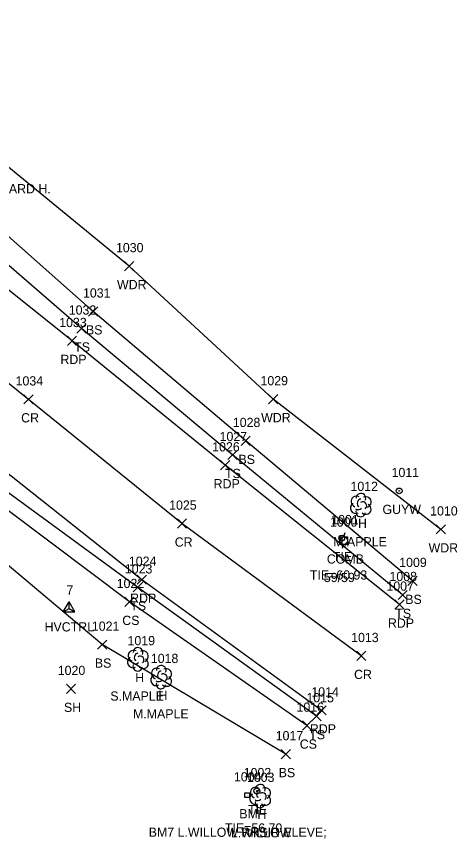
# Model space of a CAD drawing. Extents: x 1537342 to 1542195, y 163002 to 168596.
# Drawn here: x 1542099.6 to 1542195, y 163002.3 to 163180.4 of the extents above; entities that cross this region are included whole.
import ezdxf

# ---------------------------------------------------------------- set-up
doc = ezdxf.new("R2010")
doc.units = 0
for name, color, linetype in [('C_A', 7, 'Continuous'), ('C_C', 7, 'Continuous'), ('C_I', 7, 'Continuous'), ('CBP', 7, 'Continuous'), ('CPBM', 7, 'Continuous'), ('CPSM', 7, 'Continuous'), ('L_A', 7, 'Continuous'), ('L_C', 7, 'Continuous'), ('L_I', 7, 'Continuous'), ('L_TIC', 7, 'Continuous'), ('LAWA', 7, 'Continuous'), ('LELB', 7, 'Continuous'), ('LTD', 7, 'Continuous'), ('M_C', 7, 'Continuous'), ('P_A', 7, 'Continuous'), ('P_I', 7, 'Continuous'), ('P_TIC', 7, 'Continuous'), ('PET', 7, 'Continuous'), ('PRC', 7, 'Continuous'), ('U_A', 7, 'Continuous'), ('U_C', 7, 'Continuous'), ('U_I', 7, 'Continuous'), ('UP', 7, 'Continuous'), ('UPGW', 7, 'Continuous')]:
    doc.layers.add(name, color=color, linetype=linetype)

msp = doc.modelspace()

# ---------------------------------------------------------------- linework, layer by layer
at = {"layer": 'CBP'}
for centre, radius in [((1542169.95, 163067.38), 0.625), ((1542169.95, 163067.38), 0.0833), ((1542151.58, 163012.58), 0.625), ((1542151.58, 163012.58), 0.0833)]:
    msp.add_circle(centre, radius, dxfattribs=at)
at = {"layer": 'CPBM'}
for p, q in [((1542148.96, 163011.16), (1542148.96, 163012.16)), ((1542148.96, 163012.16), (1542149.96, 163012.16)), ((1542149.47, 163011.66), (1542149.47, 163011.66)), ((1542149.47, 163011.66), (1542149.47, 163011.66)), ((1542149.96, 163012.16), (1542149.96, 163011.16)), ((1542149.96, 163011.16), (1542148.96, 163011.16))]:
    msp.add_line(p, q, dxfattribs=at)
at = {"layer": 'CPSM'}
for p, q in [((1542109.7, 163051.42), (1542110.95, 163053.59)), ((1542112.2, 163051.42), (1542110.95, 163053.59)), ((1542110.95, 163052.14), (1542110.95, 163053.59)), ((1542109.7, 163051.42), (1542110.95, 163052.14)), ((1542109.7, 163051.42), (1542112.2, 163051.42)), ((1542110.95, 163052.14), (1542110.95, 163052.14)), ((1542110.95, 163052.14), (1542112.2, 163051.42))]:
    msp.add_line(p, q, dxfattribs=at)
at = {"layer": 'L_TIC'}
for points in [[(1542122.95, 163125.28), (1542124.95, 163127.28)], [(1542124.95, 163125.28), (1542122.95, 163127.28)], [(1542115.16, 163115.47), (1542117.16, 163117.47)], [(1542117.16, 163115.47), (1542115.16, 163117.47)], [(1542112.65, 163111.77), (1542114.65, 163113.77)], [(1542114.65, 163111.77), (1542112.65, 163113.77)], [(1542154.13, 163096.46), (1542156.13, 163098.46)], [(1542156.13, 163096.46), (1542154.13, 163098.46)], [(1542148.16, 163087.42), (1542150.16, 163089.42)], [(1542150.16, 163087.42), (1542148.16, 163089.42)], [(1542145.29, 163084.37), (1542147.29, 163086.37)], [(1542147.29, 163084.37), (1542145.29, 163086.37)], [(1542190.37, 163068.26), (1542192.37, 163070.26)], [(1542192.37, 163068.26), (1542190.37, 163070.26)], [(1542184.24, 163057.1), (1542186.24, 163059.1)], [(1542186.24, 163057.1), (1542184.24, 163059.1)], [(1542124.79, 163055.7), (1542126.79, 163057.7)], [(1542126.79, 163055.7), (1542124.79, 163057.7)], [(1542182.12, 163054.05), (1542184.12, 163056.05)], [(1542184.12, 163054.05), (1542182.12, 163056.05)], [(1542123.02, 163052.54), (1542125.02, 163054.54)], [(1542125.02, 163052.54), (1542123.02, 163054.54)], [(1542117.09, 163043.29), (1542119.09, 163045.29)], [(1542119.09, 163043.29), (1542117.09, 163045.29)], [(1542110.36, 163033.71), (1542112.36, 163035.71)], [(1542112.36, 163033.71), (1542110.36, 163035.71)], [(1542163.5, 163027.8), (1542165.5, 163029.8)], [(1542165.5, 163027.8), (1542163.5, 163029.8)], [(1542161.42, 163025.75), (1542163.42, 163027.75)], [(1542163.42, 163025.75), (1542161.42, 163027.75)], [(1542156.86, 163019.57), (1542158.86, 163021.57)], [(1542158.86, 163019.57), (1542156.86, 163021.57)]]:
    msp.add_lwpolyline(points, dxfattribs=at)
at = {"layer": 'LAWA'}
msp.add_lwpolyline([(1542191.37, 163069.26), (1542155.13, 163097.46), (1542123.95, 163126.28), (1542083.78, 163159.16), (1542082.85, 163172.31), (1542083.05, 163192.11), (1542078.54, 163207.24), (1542059.97, 163213.12), (1542055.91, 163226.6), (1542055.2, 163251.61), (1542037.65, 163282.73), (1542029.16, 163294.8)], dxfattribs=at)
at = {"layer": 'LELB'}
for points in [[(1542185.24, 163058.1), (1542149.16, 163088.42), (1542116.16, 163116.47), (1542076.56, 163151.51), (1542049.16, 163172.67), (1542035.85, 163185.79), (1542036.46, 163200.98), (1542035.82, 163228.32), (1542041.31, 163237.99)], [(1542183.12, 163055.05), (1542146.29, 163085.37), (1542113.65, 163112.77), (1542073.54, 163147.5), (1542044.28, 163168.18), (1542019.33, 163189.82), (1542014.69, 163194.08)], [(1542162.42, 163026.75), (1542124.02, 163053.54), (1542089.63, 163079.43)], [(1542164.5, 163028.8), (1542125.79, 163056.7), (1542093.51, 163080.24)], [(1542157.86, 163020.57), (1542118.09, 163044.29), (1542089.28, 163068.58)]]:
    msp.add_lwpolyline(points, dxfattribs=at)
at = {"layer": 'LTD'}
for p, q in [((1542174.03, 163074.57), (1542174.03, 163074.57)), ((1542174.03, 163074.57), (1542174.03, 163074.57)), ((1542125.81, 163041.16), (1542125.81, 163041.16)), ((1542125.81, 163041.16), (1542125.81, 163041.16)), ((1542130.84, 163037.3), (1542130.84, 163037.3)), ((1542130.84, 163037.3), (1542130.84, 163037.3)), ((1542152.28, 163011.55), (1542152.28, 163011.55)), ((1542152.28, 163011.55), (1542152.28, 163011.55))]:
    msp.add_line(p, q, dxfattribs=at)
for centre in [(1542174.08, 163076), (1542125.86, 163042.6), (1542130.89, 163038.74), (1542152.32, 163012.98)]:
    msp.add_arc(centre, 1.05, 335.5272, 180.9563, dxfattribs=at)
for centre, major_axis, ratio, start_param, end_param in [((1542173.24, 163075.24), (1.21, -0.51), 0.895232, 1.570796, 4.712389), ((1542173.83, 163075.03), (-0.208, -0.792), 0.645439, 3.141593, 6.283185), ((1542175.08, 163075.15), (-1.14, -0.48), 0.949671, 1.570796, 4.712389), ((1542172.95, 163073.86), (0.58, -1.04), 0.959034, 3.141593, 6.283185), ((1542173.58, 163073.82), (-0.625, -0.083), 0.423636, 0, 3.141593), ((1542174.53, 163074.4), (-0.5, 0.667), 0.989748, 3.141593, 6.283185), ((1542175.03, 163073.74), (-1.09, 0.79), 0.841452, 1.570796, 4.712389), ((1542174.03, 163073.07), (0.26, 1.06), 0.942809, 1.570796, 4.712389), ((1542125.02, 163041.83), (1.21, -0.51), 0.895232, 1.570796, 4.712389), ((1542125.61, 163041.62), (-0.208, -0.792), 0.645439, 3.141593, 6.283185), ((1542126.31, 163041), (-0.5, 0.667), 0.989748, 3.141593, 6.283185), ((1542126.86, 163041.75), (-1.14, -0.48), 0.949671, 1.570796, 4.712389), ((1542124.73, 163040.45), (0.58, -1.04), 0.959034, 3.141593, 6.283185), ((1542125.36, 163040.41), (-0.625, -0.083), 0.423636, 0, 3.141593), ((1542126.81, 163040.33), (-1.09, 0.79), 0.841452, 1.570796, 4.712389), ((1542125.81, 163039.66), (0.26, 1.06), 0.942809, 1.570796, 4.712389), ((1542130.05, 163037.97), (1.21, -0.51), 0.895232, 1.570796, 4.712389), ((1542130.64, 163037.76), (-0.208, -0.792), 0.645439, 3.141593, 6.283185), ((1542131.89, 163037.89), (-1.14, -0.48), 0.949671, 1.570796, 4.712389), ((1542129.76, 163036.59), (0.58, -1.04), 0.959034, 3.141593, 6.283185), ((1542130.39, 163036.55), (-0.625, -0.083), 0.423636, 0, 3.141593), ((1542131.34, 163037.14), (-0.5, 0.667), 0.989748, 3.141593, 6.283185), ((1542131.84, 163036.47), (-1.09, 0.79), 0.841452, 1.570796, 4.712389), ((1542130.84, 163035.8), (0.26, 1.06), 0.942809, 1.570796, 4.712389), ((1542151.48, 163012.21), (1.21, -0.51), 0.895232, 1.570796, 4.712389), ((1542153.32, 163012.13), (-1.14, -0.48), 0.949671, 1.570796, 4.712389), ((1542151.19, 163010.84), (0.58, -1.04), 0.959034, 3.141593, 6.283185), ((1542152.07, 163012.01), (-0.208, -0.792), 0.645439, 3.141593, 6.283185), ((1542152.78, 163011.38), (-0.5, 0.667), 0.989748, 3.141593, 6.283185), ((1542153.28, 163010.71), (-1.09, 0.79), 0.841452, 1.570796, 4.712389), ((1542152.28, 163010.05), (0.26, 1.06), 0.942809, 1.570796, 4.712389), ((1542151.82, 163010.8), (-0.625, -0.083), 0.423636, 0, 3.141593)]:
    msp.add_ellipse(centre, major_axis=major_axis, ratio=ratio, start_param=start_param, end_param=end_param, dxfattribs=at)
at = {"layer": 'P_TIC'}
for points in [[(1542110.59, 163109.07), (1542112.59, 163111.07)], [(1542112.59, 163109.07), (1542110.59, 163111.07)], [(1542101.15, 163096.42), (1542103.15, 163098.42)], [(1542103.15, 163096.42), (1542101.15, 163098.42)], [(1542143.74, 163082.14), (1542145.74, 163084.14)], [(1542145.74, 163082.14), (1542143.74, 163084.14)], [(1542134.38, 163069.51), (1542136.38, 163071.51)], [(1542136.38, 163069.51), (1542134.38, 163071.51)], [(1542125.67, 163057.36), (1542127.67, 163059.36)], [(1542127.67, 163057.36), (1542125.67, 163059.36)], [(1542181.46, 163051.97), (1542183.46, 163053.97)], [(1542183.46, 163051.97), (1542181.46, 163053.97)], [(1542173.18, 163040.84), (1542175.18, 163042.84)], [(1542175.18, 163040.84), (1542173.18, 163042.84)], [(1542164.56, 163029.05), (1542166.56, 163031.05)], [(1542166.56, 163029.05), (1542164.56, 163031.05)]]:
    msp.add_lwpolyline(points, dxfattribs=at)
at = {"layer": 'PET'}
for points in [[(1542165.56, 163030.05), (1542126.67, 163058.36), (1542096.32, 163082.47), (1542058.61, 163112.54), (1542052.02, 163117.84), (1542010.73, 163151.35), (1541978.73, 163177.48), (1541958.58, 163193.33), (1541928.58, 163217.89), (1541894.65, 163244.61), (1541857.53, 163271.04), (1541839.6, 163283.45), (1541795.58, 163311.16), (1541814.19, 163318.82), (1541832.22, 163326.69)], [(1542182.46, 163052.97), (1542144.74, 163083.14), (1542111.59, 163110.07), (1542069.86, 163143.45), (1542042.93, 163166.04), (1542014.58, 163189.13), (1541996.52, 163203.32), (1541975.27, 163220.84), (1541953.96, 163238.23), (1541914.85, 163268.66), (1541894.39, 163285), (1541874.19, 163298.08), (1541854.83, 163311.47), (1541832.22, 163326.69)]]:
    msp.add_lwpolyline(points, dxfattribs=at)
at = {"layer": 'PRC'}
msp.add_lwpolyline([(1542174.18, 163041.84), (1542135.38, 163070.51), (1542102.15, 163097.42), (1542058.02, 163132.98), (1542032.76, 163153.88), (1541982.81, 163194.28), (1541947.35, 163222.57), (1541904.32, 163256.11), (1541874.29, 163278.53), (1541825.99, 163311), (1541814.19, 163318.82)], dxfattribs=at)
at = {"layer": 'UP'}
for p, q in [((1542170.59, 163068.51), (1542170.34, 163067.67)), ((1542169.5, 163066.01), (1542169.5, 163067.67)), ((1542169.5, 163067.67), (1542171.17, 163067.67)), ((1542170.34, 163066.84), (1542170.34, 163066.84)), ((1542171.17, 163067.67), (1542171.17, 163066.01)), ((1542171.17, 163066.01), (1542169.5, 163066.01)), ((1542170.09, 163065.17), (1542170.34, 163066.01))]:
    msp.add_line(p, q, dxfattribs=at)
msp.add_circle((1542170.34, 163066.84), 0.833, dxfattribs=at)
at = {"layer": 'UPGW'}
for radius in [0.625, 0.0833]:
    msp.add_circle((1542182.37, 163077.58), radius, dxfattribs=at)

# ---------------------------------------------------------------- texts
at = {"layer": 'C_A'}
for s, p in [('TIE', (1542168.03, 163062.38)), ('HVCTRL', (1542105.65, 163047.14)), ('BM', (1542147.78, 163006.66)), ('TIE', (1542149.66, 163007.58))]:
    msp.add_text(s, height=2, dxfattribs=at).set_placement(p)
at = {"layer": 'C_C'}
for s, p in [('TIE=60.93', (1542163.05, 163058.38)), ('BM7 L.WILLOW RRSIR ELEVE;', (1542128.18, 163002.66)), ('TIE=56.70', (1542144.67, 163003.58))]:
    msp.add_text(s, height=2, dxfattribs=at).set_placement(p)
at = {"layer": 'C_I'}
for s, p in [('1001', (1542167.67, 163070.38)), ('7', (1542110.39, 163055.14)), ('1002', (1542148.73, 163015.58)), ('1004', (1542146.62, 163014.66))]:
    msp.add_text(s, height=2, dxfattribs=at).set_placement(p)
at = {"layer": 'L_A'}
for s, p in [('WDR', (1542121.32, 163121.28)), ('BS', (1542114.6, 163111.47)), ('TS', (1542112.06, 163107.77)), ('WDR', (1542152.5, 163092.46)), ('BS', (1542147.6, 163083.42)), ('TS', (1542144.7, 163080.37)), ('H', (1542173.47, 163069.57)), ('WDR', (1542188.73, 163064.26)), ('BS', (1542183.68, 163053.1)), ('TS', (1542124.2, 163051.7)), ('TS', (1542181.53, 163050.05)), ('CS', (1542122.46, 163048.54)), ('BS', (1542116.53, 163039.29)), ('H', (1542125.25, 163036.16)), ('H', (1542130.28, 163032.3)), ('SH', (1542109.85, 163029.71)), ('TS', (1542162.91, 163023.8)), ('CS', (1542160.86, 163021.75)), ('BS', (1542156.3, 163015.57)), ('H', (1542151.71, 163006.55))]:
    msp.add_text(s, height=2, dxfattribs=at).set_placement(p)
at = {"layer": 'L_C'}
for s, p in [('M.APPLE', (1542168.1, 163065.57)), ('S.MAPLE', (1542119.88, 163032.16)), ('M.MAPLE', (1542124.78, 163028.3)), ('L.WILLOW', (1542145.98, 163002.55))]:
    msp.add_text(s, height=2, dxfattribs=at).set_placement(p)
at = {"layer": 'L_I'}
for s, p in [('1030', (1542121.1, 163129.28)), ('1031', (1542113.96, 163119.47)), ('1032', (1542110.88, 163115.77)), ('1029', (1542152.36, 163100.46)), ('1028', (1542146.38, 163091.42)), ('1027', (1542143.52, 163088.37)), ('1012', (1542171.83, 163077.57)), ('1010', (1542189.08, 163072.26)), ('1009', (1542182.38, 163061.1)), ('1023', (1542123.02, 163059.7)), ('1008', (1542180.27, 163058.05)), ('1022', (1542121.25, 163056.54)), ('1021', (1542115.88, 163047.29)), ('1019', (1542123.6, 163044.16)), ('1018', (1542128.64, 163040.3)), ('1020', (1542108.5, 163037.71)), ('1015', (1542162.3, 163031.8)), ('1016', (1542160.16, 163029.75)), ('1017', (1542155.65, 163023.57)), ('1003', (1542149.43, 163014.55))]:
    msp.add_text(s, height=2, dxfattribs=at).set_placement(p)
at = {"layer": 'M_C'}
msp.add_text('5/8" REBAR W/ CAP RICHARD H.', height=2, dxfattribs=at).set_placement((1542065.77, 163142.04))
at = {"layer": 'P_A'}
for s, p in [('RDP', (1542109.08, 163105.07)), ('CR', (1542100.58, 163092.42)), ('RDP', (1542142.23, 163078.14)), ('CR', (1542133.81, 163065.51)), ('RDP', (1542124.16, 163053.36)), ('RDP', (1542179.94, 163047.97)), ('CR', (1542172.61, 163036.84)), ('RDP', (1542163.05, 163025.05))]:
    msp.add_text(s, height=2, dxfattribs=at).set_placement(p)
at = {"layer": 'P_I'}
for s, p in [('1033', (1542108.82, 163113.07)), ('1034', (1542099.38, 163100.42)), ('1026', (1542141.92, 163086.14)), ('1025', (1542132.6, 163073.51)), ('1024', (1542123.9, 163061.36)), ('1007', (1542179.61, 163055.97)), ('1013', (1542171.98, 163044.84)), ('1014', (1542163.36, 163033.05))]:
    msp.add_text(s, height=2, dxfattribs=at).set_placement(p)
at = {"layer": 'U_A'}
for s, p in [('GUYW', (1542178.76, 163072.58)), ('COMB', (1542166.72, 163061.84))]:
    msp.add_text(s, height=2, dxfattribs=at).set_placement(p)
at = {"layer": 'U_C'}
msp.add_text('59/59', height=2, dxfattribs=at).set_placement((1542166.09, 163057.84))
at = {"layer": 'U_I'}
for s, p in [('1011', (1542180.73, 163080.58)), ('1000', (1542167.4, 163069.84))]:
    msp.add_text(s, height=2, dxfattribs=at).set_placement(p)

doc.saveas('drawing.dxf')
